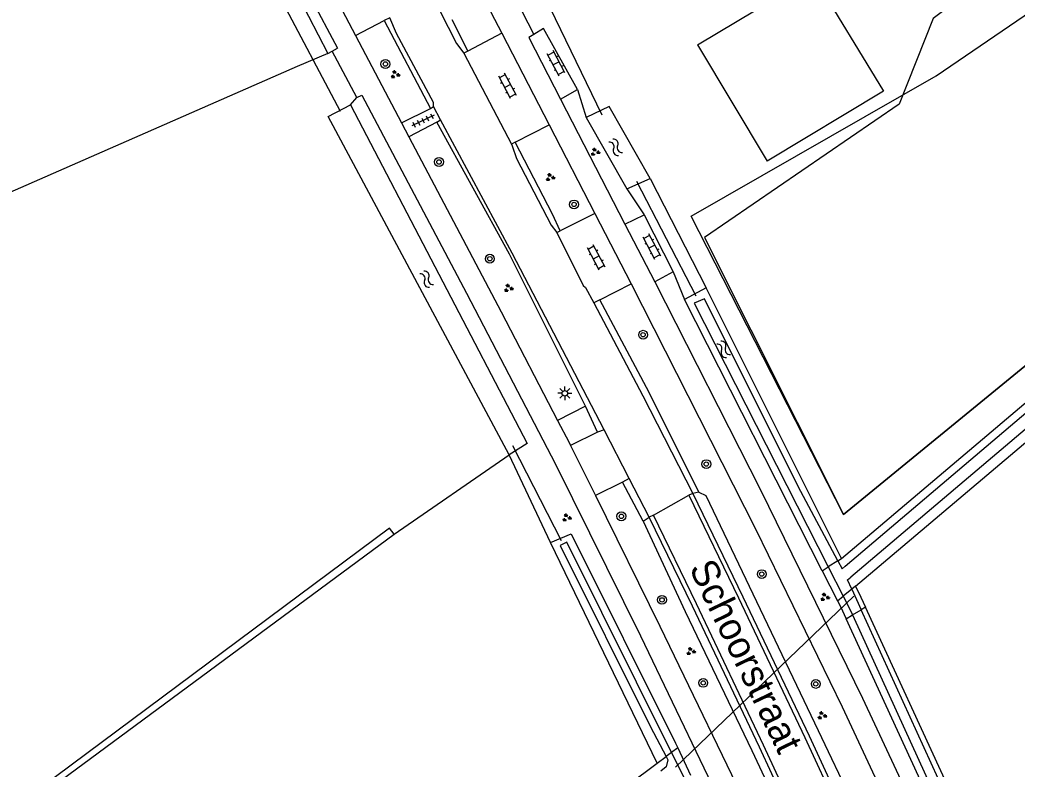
# Model space of a CAD drawing. Extents: x 134297 to 137000, y 403500 to 406000.
# Drawn here: x 136017.8 to 136108.6, y 404828.7 to 404896.9 of the extents above; entities that cross this region are included whole.
import ezdxf

# ---------------------------------------------------------------- set-up
doc = ezdxf.new("R2010")
doc.units = 0
for name, color, linetype in [('gg-afsc-hekwerk', 7, 'Continuous'), ('gg-afsc-lijn draadraster', 7, 'Continuous'), ('gg-anno-openbare ruimte label', 7, 'Continuous'), ('gg-bbg-open loods', 7, 'Continuous'), ('gg-knt-bronhoudergrens', 7, 'Continuous'), ('gg-knt-verharding', 7, 'Continuous'), ('gg-knt-verharding nz', 7, 'Continuous'), ('gg-kntw-bovenkant insteek waterloop', 7, 'Continuous'), ('gg-kntw-waterlijn', 7, 'Continuous'), ('gg-kwrk-duiker nz buis', 7, 'Continuous'), ('gt-grn-groengrens', 7, 'Continuous'), ('gt-grn-vlakafsluiter', 7, 'Continuous'), ('gt-grn-weggrens', 7, 'Continuous'), ('gt-symb-boom', 7, 'Continuous'), ('gt-symb-groenvak', 7, 'Continuous'), ('gt-symb-klinker verharding', 7, 'Continuous'), ('gt-symb-lichtmast', 7, 'Continuous'), ('gt-symb-tegel verharding', 7, 'Continuous'), ('gt-symb-watersymbool', 7, 'Continuous')]:
    doc.layers.add(name, color=color, linetype=linetype)

# ---------------------------------------------------------------- blocks, each defined once
blk = doc.blocks.new('gt0-KL1')
at = {"layer": 'gt-symb-klinker verharding'}
for p, q in [((-1.15, 0.3), (1.15, 0.3)), ((-1, -0.3), (-1, 0.3)), ((-0.5, 0.3), (-0.5, 0.45)), ((0, -0.3), (0, 0.3)), ((0.5, 0.3), (0.5, 0.45)), ((1, -0.3), (1, 0.3)), ((-1.15, -0.3), (1.15, -0.3)), ((-0.5, -0.45), (-0.5, -0.3)), ((0.5, -0.45), (0.5, -0.3))]:
    blk.add_line(p, q, dxfattribs=at)
blk = doc.blocks.new('gt0-BOOM')
at = {"layer": 'gt-symb-boom'}
for radius in [0.4, 0.2]:
    blk.add_circle((0, 0), radius, dxfattribs=at)
blk = doc.blocks.new('gt0-GRVAK')
at = {"layer": 'gt-symb-groenvak'}
for p, q in [((-0.11, 0.189), (-0.228, 0.24)), ((-0.182, 0.153), (0.088, 0.153)), ((-0.091, 0.211), (-0.156, 0.322)), ((-0.047, 0.214), (-0.047, 0.393)), ((-0.004, 0.211), (0.061, 0.322)), ((0.015, 0.189), (0.133, 0.24)), ((0.262, -0.052), (0.197, 0.059)), ((0.305, -0.049), (0.305, 0.13)), ((0.349, -0.052), (0.414, 0.059)), ((-0.245, -0.228), (-0.363, -0.177)), ((-0.318, -0.264), (-0.047, -0.264)), ((-0.226, -0.206), (-0.291, -0.095)), ((-0.183, -0.203), (-0.183, -0.024)), ((-0.139, -0.206), (-0.074, -0.095)), ((-0.12, -0.228), (-0.002, -0.177)), ((0.243, -0.074), (0.125, -0.023)), ((0.17, -0.11), (0.441, -0.11)), ((0.368, -0.074), (0.486, -0.023))]:
    blk.add_line(p, q, dxfattribs=at)
blk = doc.blocks.new('gt0-WA')
at = {"layer": 'gt-symb-watersymbool'}
for centre, start, end in [((-0.323, 0.022), 28.07249, 151.92751), ((0.427, 0.422), 208.07248, 331.92751), ((-0.323, -0.428), 28.07249, 151.92751), ((0.427, -0.028), 208.07248, 331.92751)]:
    blk.add_arc(centre, 0.425, start, end, dxfattribs=at)
blk = doc.blocks.new('gt0-LMAST')
at = {"layer": 'gt-symb-lichtmast'}
for p, q in [((-0.182, 0.173), (-0.447, 0.438)), ((-0.005, 0.246), (-0.005, 0.621)), ((0.172, 0.173), (0.437, 0.438)), ((-0.255, -0.004), (-0.63, -0.004)), ((-0.182, -0.181), (-0.447, -0.446)), ((-0.005, -0.254), (-0.005, -0.629)), ((0.437, -0.446), (0.172, -0.181)), ((0.245, -0.004), (0.62, -0.004))]:
    blk.add_line(p, q, dxfattribs=at)
blk.add_circle((-0.005, -0.004), 0.25, dxfattribs=at)
blk = doc.blocks.new('gt0-TEG1')
at = {"layer": 'gt-symb-tegel verharding'}
for p, q in [((-1.125, 0), (1.125, 0)), ((-0.9, -0.25), (-0.9, 0.25)), ((-0.45, -0.25), (-0.45, 0.25)), ((0, -0.25), (0, 0.25)), ((0.45, -0.25), (0.45, 0.25)), ((0.9, -0.25), (0.9, 0.25))]:
    blk.add_line(p, q, dxfattribs=at)

msp = doc.modelspace()

# ---------------------------------------------------------------- linework, layer by layer
at = {"layer": 'gg-afsc-hekwerk'}
msp.add_line((136042.59, 404900.212), (136045.861, 404893.829), dxfattribs=at)
at = {"layer": 'gg-afsc-lijn draadraster'}
for points in [[(136078.949, 404879.021), (136101.24, 404891.787), (136115.924, 404901.841), (136121.813, 404906.367), (136129.839, 404918.688), (136134.626, 404922.291), (136129.817, 404928.09), (136115.421, 404941.726), (136110.224, 404945.696), (136104.336, 404942.156), (136096.213, 404951.318), (136087.217, 404961.24), (136080.547, 404969.352)], [(136152.481, 404896.313), (136150.717, 404898.918), (136143.989, 404893.745), (136092.823, 404851.851), (136078.949, 404879.021)]]:
    msp.add_lwpolyline(points, dxfattribs=at)
at = {"layer": 'gg-bbg-open loods'}
msp.add_line((136079.531, 404894.612), (136085.871, 404884.031), dxfattribs=at)
msp.add_lwpolyline([(136079.531, 404894.612), (136090.044, 404900.92), (136096.455, 404890.396), (136085.871, 404884.031)], dxfattribs=at)
at = {"layer": 'gg-knt-bronhoudergrens'}
msp.add_line((136051.902, 404850.062), (136062.384, 404857.297), dxfattribs=at)
msp.add_lwpolyline([(136080.547, 404969.352), (136087.217, 404961.24), (136100.311, 404942.781), (136113.706, 404948.569), (136129.817, 404928.09), (136134.626, 404922.291), (136100.963, 404896.995), (136097.867, 404889.216), (136080.166, 404877.072), (136092.823, 404851.851), (136143.989, 404893.745), (136150.717, 404898.918), (136152.481, 404896.313)], dxfattribs=at)
at = {"layer": 'gg-knt-verharding'}
for p, q in [((136054.633, 404909.364), (136061.698, 404895.673)), ((136048.39, 404895.469), (136050.989, 404896.835)), ((136051.508, 404897.067), (136050.989, 404896.835)), ((136050.989, 404896.835), (136055.209, 404888.822)), ((136057.155, 404896.918), (136058.601, 404894.04)), ((136061.698, 404895.673), (136058.601, 404894.04)), ((136061.698, 404895.673), (136066.009, 404887.319)), ((136048.39, 404895.469), (136052.591, 404887.506)), ((136045.861, 404893.829), (136046.26, 404894.039)), ((136046.26, 404894.039), (136046.746, 404894.296)), ((136048.509, 404889.804), (136046.26, 404894.039)), ((136058.601, 404894.04), (136058.242, 404893.851)), ((136058.242, 404893.851), (136062.588, 404885.575)), ((136067.05, 404889.671), (136068.614, 404890.561)), ((136067.05, 404889.671), (136072.919, 404878.29)), ((136052.591, 404887.506), (136055.209, 404888.822)), ((136055.209, 404888.822), (136055.5, 404888.991)), ((136056.138, 404887.786), (136055.5, 404888.991)), ((136055.805, 404887.569), (136053.252, 404886.253)), ((136055.805, 404887.569), (136056.138, 404887.786)), ((136062.914, 404885.741), (136066.009, 404887.319)), ((136066.009, 404887.319), (136070.167, 404879.262)), ((136062.914, 404885.741), (136062.588, 404885.575)), ((136070.167, 404879.262), (136067.017, 404877.687)), ((136070.167, 404879.262), (136073.476, 404872.85)), ((136072.919, 404878.29), (136074.681, 404879.126)), ((136072.919, 404878.29), (136075.627, 404873.037)), ((136074.681, 404879.126), (136077.304, 404873.96)), ((136066.708, 404877.533), (136067.017, 404877.687)), ((136077.304, 404873.96), (136075.627, 404873.037)), ((136070.635, 404871.409), (136073.476, 404872.85)), ((136070.635, 404871.409), (136070.091, 404871.133)), ((136070.412, 404859.353), (136069.323, 404861.736)), ((136066.783, 404860.422), (136067.827, 404858.406)), ((136070.412, 404859.353), (136067.963, 404858.133)), ((136071.013, 404859.561), (136070.412, 404859.353)), ((136073.313, 404855.149), (136071.013, 404859.561)), ((136067.827, 404858.406), (136067.963, 404858.133)), ((136067.963, 404858.133), (136070.229, 404853.584)), ((136072.698, 404854.814), (136070.229, 404853.584)), ((136073.313, 404855.149), (136072.698, 404854.814)), ((136074.571, 404851.25), (136072.698, 404854.814)), ((136075.134, 404851.61), (136073.313, 404855.149)), ((136079.1, 404853.779), (136078.742, 404853.611)), ((136079.64, 404853.883), (136079.1, 404853.779)), ((136074.571, 404851.25), (136075.134, 404851.61)), ((136075.504, 404851.808), (136075.134, 404851.61))]:
    msp.add_line(p, q, dxfattribs=at)
for points in [[(136046.282, 404930.093), (136046.75, 404930.315), (136064.609, 404895.537)], [(136051.308, 404907.67), (136051.485, 404906.715), (136057.589, 404894.718), (136058.242, 404893.851)], [(136055.5, 404888.991), (136055.495, 404889.357), (136052.137, 404895.656), (136051.508, 404897.067)], [(136064.609, 404895.537), (136064.162, 404895.273), (136067.05, 404889.671)], [(136068.614, 404890.561), (136065.515, 404896.085), (136064.609, 404895.537)], [(136048.509, 404889.804), (136048.959, 404890.03), (136058.488, 404872.005), (136066.583, 404856.45), (136074.328, 404840.82), (136082.99, 404822.797), (136092.975, 404801.099)], [(136069.323, 404861.736), (136062.398, 404875.544), (136055.805, 404887.569)], [(136071.013, 404859.561), (136062.664, 404875.656), (136056.138, 404887.786)], [(136053.252, 404886.253), (136061.665, 404870.308), (136066.783, 404860.422)], [(136062.588, 404885.575), (136062.664, 404885.428), (136063.056, 404884.251), (136066.197, 404878.2), (136066.708, 404877.533)], [(136067.017, 404877.687), (136066.314, 404879.191), (136062.914, 404885.741)], [(136066.708, 404877.533), (136069.103, 404872.712), (136069.329, 404872.525), (136070.091, 404871.133)], [(136073.476, 404872.85), (136084.839, 404850.49), (136092.693, 404834.358), (136099.469, 404819.871), (136105.839, 404805.783)], [(136075.627, 404873.037), (136085.264, 404854.098), (136094.535, 404835.162), (136100.46, 404822.511), (136117.795, 404784.255), (136127.935, 404761.691)], [(136070.091, 404871.133), (136074.543, 404862.65), (136079.1, 404853.779)], [(136079.64, 404853.883), (136075.135, 404862.97), (136070.635, 404871.409)], [(136079.1, 404853.779), (136083.656, 404844.377), (136089.676, 404831.711), (136095.672, 404818.78), (136101.568, 404805.934)], [(136070.229, 404853.584), (136076.106, 404841.686), (136084.793, 404823.685), (136093.871, 404803.957)], [(136078.742, 404853.611), (136083.252, 404844.274), (136089.288, 404831.558), (136095.316, 404818.592), (136101.207, 404805.766)], [(136096.357, 404806.368), (136090.794, 404818.561), (136085.164, 404830.7), (136079.082, 404843.521), (136075.134, 404851.61)], [(136096.73, 404806.539), (136091.158, 404818.752), (136085.541, 404830.878), (136079.44, 404843.719), (136075.504, 404851.808)]]:
    msp.add_lwpolyline(points, dxfattribs=at)
at = {"layer": 'gg-knt-verharding nz'}
for p, q in [((136045.278, 404901.369), (136048.39, 404895.469)), ((136043.398, 404900.638), (136046.746, 404894.296))]:
    msp.add_line(p, q, dxfattribs=at)
at = {"layer": 'gg-kntw-bovenkant insteek waterloop'}
for p, q in [((136069.398, 404887.995), (136073.075, 404881.501)), ((136073.075, 404881.501), (136075.202, 404882.448)), ((136080.319, 404872.5), (136078.328, 404871.418)), ((136092.631, 404847.873), (136080.319, 404872.5)), ((136090.882, 404846.731), (136078.328, 404871.418)), ((136075.842, 404829.221), (136066.148, 404849.307)), ((136090.882, 404846.731), (136092.259, 404844.021)), ((136110.523, 404809.315), (136094.816, 404843.428)), ((136077.73, 404830.638), (136078.9, 404828.127))]:
    msp.add_line(p, q, dxfattribs=at)
for points in [[(135883.808, 404947.37), (135892.616, 404923.501), (135909.579, 404876.1), (135922.545, 404840.236), (135939.63, 404792.038), (135946.813, 404772.204), (135989.291, 404803.836), (136051.902, 404850.062)], [(136092.631, 404847.873), (136121.29, 404872.09), (136136.773, 404885.502), (136151.686, 404896.283)], [(136093.898, 404845.338), (136123.319, 404870.197), (136138.801, 404883.609), (136153.714, 404894.39)], [(136062.384, 404857.297), (136045.908, 404888.101), (136047.92, 404889.161)], [(136047.92, 404889.161), (136064.027, 404858.327), (136062.384, 404857.297)], [(136075.202, 404882.448), (136071.475, 404888.984), (136069.398, 404887.995)], [(136051.902, 404850.062), (136051.496, 404850.62), (136001.809, 404813.68), (135947.256, 404773.449), (135943.407, 404783.069), (135929.186, 404822.736), (135912.064, 404871.084), (135906.64, 404886.478)], [(136066.148, 404849.307), (136068.014, 404850.095), (136077.534, 404831.059), (136077.73, 404830.638)], [(136093.898, 404845.338), (136094.391, 404844.352), (136094.816, 404843.428)], [(136092.259, 404844.021), (136092.533, 404843.483), (136093.043, 404842.376)], [(136110.523, 404809.315), (136108.665, 404808.446), (136093.043, 404842.376)], [(135888.636, 404688.406), (136009.805, 404779.906), (136075.842, 404829.221)]]:
    msp.add_lwpolyline(points, dxfattribs=at)
at = {"layer": 'gg-kntw-waterlijn'}
for p, q in [((136091.429, 404847.088), (136092.778, 404844.438)), ((136093.569, 404845.074), (136094.426, 404843.197)), ((136078.401, 404827.735), (136077.166, 404830.214))]:
    msp.add_line(p, q, dxfattribs=at)
for points in [[(136092.979, 404847.177), (136128.074, 404876.95), (136137.23, 404884.548), (136144.988, 404890.382), (136151.962, 404895.312)], [(136152.581, 404894.435), (136142.114, 404887.049), (136137.926, 404884.015), (136123.036, 404871.177), (136093.483, 404846.168)], [(136092.295, 404847.653), (136088.695, 404854.398), (136080.173, 404871.484), (136079.208, 404871.112), (136091.429, 404847.088)], [(136077.166, 404830.214), (136067.624, 404849.36), (136067.012, 404849.055), (136075.24, 404832.545), (136076.665, 404829.839)], [(136092.295, 404847.653), (136092.683, 404846.926), (136092.979, 404847.177)], [(136093.569, 404845.074), (136093.185, 404845.916), (136093.483, 404846.168)], [(136092.778, 404844.438), (136093.474, 404843.069), (136093.631, 404842.725)], [(136093.631, 404842.725), (136108.891, 404809.301), (136109.727, 404809.682), (136094.426, 404843.197)], [(136076.665, 404829.839), (136076.824, 404829.537), (136076.679, 404828.887), (136076.182, 404828.517)]]:
    msp.add_lwpolyline(points, dxfattribs=at)
at = {"layer": 'gg-kwrk-duiker nz buis'}
for p, q in [((136047.039, 404888.529), (136020.811, 404938.12)), ((136070.856, 404888.222), (136047.341, 404936.75)), ((136073.963, 404882.202), (136079.379, 404871.754)), ((136067.152, 404849.458), (136062.703, 404858.099)), ((136093.76, 404844.436), (136077.512, 404828.875))]:
    msp.add_line(p, q, dxfattribs=at)
at = {"layer": 'gt-grn-groengrens'}
for p, q in [((136068.614, 404890.561), (136069.398, 404887.995)), ((136047.92, 404889.161), (136048.509, 404889.804)), ((136075.202, 404882.448), (136080.319, 404872.5)), ((136073.075, 404881.501), (136074.681, 404879.126)), ((136077.304, 404873.96), (136078.328, 404871.418)), ((136069.323, 404861.736), (136066.783, 404860.422)), ((136066.148, 404849.307), (136062.384, 404857.297))]:
    msp.add_line(p, q, dxfattribs=at)
for points in [[(136045.861, 404893.829), (136043.079, 404892.654), (135976.145, 404863.291), (135953.371, 404908.112), (135906.64, 404886.478)], [(136079.64, 404853.883), (136080.27, 404853.588), (136090.495, 404832.203), (136096.626, 404819.334), (136102.567, 404805.593)], [(136074.571, 404851.25), (136078.385, 404843.038), (136084.471, 404830.373), (136090.196, 404818.165), (136095.248, 404806.867), (136094.968, 404804.462), (136093.871, 404803.957)]]:
    msp.add_lwpolyline(points, dxfattribs=at)
at = {"layer": 'gt-grn-vlakafsluiter'}
for p, q in [((136092.295, 404847.653), (136091.429, 404847.088)), ((136092.295, 404847.653), (136092.631, 404847.873)), ((136090.882, 404846.731), (136091.429, 404847.088)), ((136093.569, 404845.074), (136092.778, 404844.438)), ((136093.898, 404845.338), (136093.569, 404845.074)), ((136092.259, 404844.021), (136092.778, 404844.438)), ((136093.631, 404842.725), (136094.426, 404843.197)), ((136094.816, 404843.428), (136094.426, 404843.197)), ((136093.043, 404842.376), (136093.631, 404842.725)), ((136077.166, 404830.214), (136076.665, 404829.839)), ((136077.73, 404830.638), (136077.166, 404830.214)), ((136075.842, 404829.221), (136076.665, 404829.839))]:
    msp.add_line(p, q, dxfattribs=at)
at = {"layer": 'gt-grn-weggrens'}
for p, q in [((136052.591, 404887.506), (136053.252, 404886.253)), ((136075.504, 404851.808), (136078.742, 404853.611))]:
    msp.add_line(p, q, dxfattribs=at)

# ---------------------------------------------------------------- block references
at = {"layer": 'gt-symb-boom'}
for p in [(136051.11, 404892.865), (136055.993, 404883.949), (136068.284, 404880.085), (136060.617, 404875.145), (136074.568, 404868.227), (136080.323, 404856.451), (136072.593, 404851.699), (136085.372, 404846.441), (136076.29, 404844.093), (136080.048, 404836.537), (136090.286, 404836.442)]:
    msp.add_blockref('gt0-BOOM', p, dxfattribs=at)
at = {"layer": 'gt-symb-groenvak'}
for p in [(136051.987, 404891.901), (136070.202, 404884.849), (136066.099, 404882.548), (136062.312, 404872.468), (136067.601, 404851.569), (136091.103, 404844.343), (136078.911, 404839.406), (136090.85, 404833.563)]:
    msp.add_blockref('gt0-GRVAK', p, dxfattribs=at)
at = {"layer": 'gt-symb-klinker verharding'}
for p, rotation in [((136066.652, 404892.926), 117.97472992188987), ((136062.234, 404890.874), 117.97472992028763), ((136075.367, 404876.243), 117.97472991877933), ((136070.3, 404875.255), 117.9747299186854)]:
    msp.add_blockref('gt0-KL1', p, dxfattribs=dict(at, rotation=rotation))
at = {"layer": 'gt-symb-lichtmast'}
msp.add_blockref('gt0-LMAST', (136067.451, 404862.899), dxfattribs=at)
at = {"layer": 'gt-symb-tegel verharding', "rotation": -154.10085101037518}
msp.add_blockref('gt0-TEG1', (136054.527, 404887.726), dxfattribs=at)
at = {"layer": 'gt-symb-watersymbool'}
for p, rotation in [((136072.099, 404885.248), 126.01052540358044), ((136054.893, 404873.236), 126.01052540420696), ((136081.922, 404866.863), 126.01052540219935)]:
    msp.add_blockref('gt0-WA', p, dxfattribs=dict(at, rotation=rotation))

# ---------------------------------------------------------------- texts
at = {"layer": 'gg-anno-openbare ruimte label'}
msp.add_text('Schoorstraat', height=2.5, rotation=295.7, dxfattribs=at).set_placement((136078.724, 404846.996))

doc.saveas('drawing.dxf')
